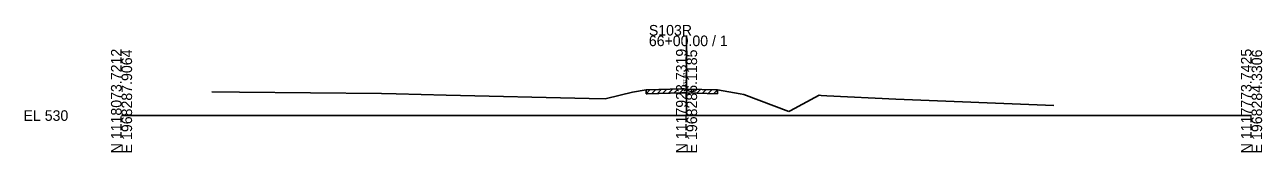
# Model space of a CAD drawing. Extents: x 974 to 1303, y 990 to 10019.
# Drawn here: x 974.3 to 1302.8, y 8490.3 to 8524 of the extents above; entities that cross this region are included whole.
import ezdxf

# ---------------------------------------------------------------- set-up
doc = ezdxf.new("R2010")
doc.units = 0
for name, color, linetype in [('Level 10', 7, 'Continuous'), ('Level 60', 7, 'Continuous'), ('Level 61', 7, 'Continuous'), ('Level 63', 7, 'Continuous')]:
    doc.layers.add(name, color=color, linetype=linetype)

msp = doc.modelspace()

# ---------------------------------------------------------------- linework, layer by layer
at = {"layer": 'Level 60'}
for p, q in [((1024, 8506.26), (1031.36, 8506.23)), ((1031.36, 8506.23), (1069.05, 8505.88)), ((1069.05, 8505.88), (1072.95, 8505.79)), ((1072.95, 8505.79), (1086.16, 8505.43)), ((1128.72, 8504.53), (1135.67, 8506.19)), ((1135.67, 8506.19), (1139.25, 8506.79)), ((1139.25, 8506.79), (1139.55, 8506.8)), ((1139.55, 8506.8), (1148.78, 8507.06)), ((1148.78, 8507.06), (1149.33, 8507.05)), ((1149.33, 8507.05), (1150, 8507.03)), ((1150, 8507.03), (1158.23, 8506.79)), ((1158.23, 8506.79), (1164.22, 8505.77)), ((1164.22, 8505.77), (1165.18, 8505.61)), ((1086.16, 8505.43), (1124.11, 8504.53)), ((1124.11, 8504.53), (1128.37, 8504.44)), ((1128.37, 8504.44), (1128.72, 8504.53)), ((1165.18, 8505.61), (1177.16, 8501.04)), ((1177.52, 8501.23), (1185.23, 8505.38)), ((1185.23, 8505.38), (1185.77, 8505.3)), ((1185.77, 8505.3), (1187.25, 8505.27)), ((1187.25, 8505.27), (1205.59, 8504.32)), ((1205.59, 8504.32), (1247.5, 8502.64)), ((1177.16, 8501.04), (1177.52, 8501.23))]:
    msp.add_line(p, q, dxfattribs=at)
at = {"layer": 'Level 61'}
for p, q in [((1139.25, 8505.79), (1140.28, 8506.82)), ((1139.25, 8505.79), (1139.25, 8506.79)), ((1139.25, 8505.79), (1139.55, 8505.8)), ((1139.55, 8505.8), (1148.78, 8506.06)), ((1140.75, 8505.83), (1141.78, 8506.86)), ((1142.25, 8505.87), (1143.28, 8506.9)), ((1143.75, 8505.92), (1144.78, 8506.95)), ((1145.25, 8505.96), (1146.28, 8506.99)), ((1146.75, 8506), (1147.78, 8507.03)), ((1148.25, 8506.05), (1149.25, 8507.05)), ((1148.78, 8506.06), (1149.33, 8506.05)), ((1149.33, 8506.05), (1150, 8506.03)), ((1149.75, 8506.03), (1150.72, 8507.01)), ((1150, 8506.03), (1158.23, 8505.79)), ((1151.25, 8505.99), (1152.22, 8506.96)), ((1152.75, 8505.95), (1153.72, 8506.92)), ((1154.25, 8505.9), (1155.22, 8506.87)), ((1155.75, 8505.86), (1156.72, 8506.83)), ((1157.25, 8505.82), (1158.22, 8506.79)), ((1158.23, 8506.79), (1158.23, 8505.79))]:
    msp.add_line(p, q, dxfattribs=at)
at = {"layer": 'Level 63'}
for p, q in [((1150, 8500), (1150, 8521.19)), ((1000, 8500), (1150, 8500)), ((1150, 8500), (1300, 8500))]:
    msp.add_line(p, q, dxfattribs=at)

# ---------------------------------------------------------------- texts
at = {"layer": 'Level 10'}
msp.add_text('537.03', height=0.9, rotation=90, dxfattribs=at).set_placement((1149.95, 8507.53))
at = {"layer": 'Level 63'}
for s, p in [('S103R', (1140, 8521.19)), ('66+00.00 / 1', (1140, 8518.39)), ('EL 530', (974, 8498.6))]:
    msp.add_text(s, height=2.8, dxfattribs=at).set_placement(p)
for s, p in [('N 1118073.7212', (1000, 8490)), ('E 1968287.9064', (1002.8, 8490)), ('N 1117923.7319', (1150, 8490)), ('E 1968286.1185', (1152.8, 8490)), ('N 1117773.7425', (1300, 8490)), ('E 1968284.3306', (1302.8, 8490))]:
    msp.add_text(s, height=2.8, rotation=90, dxfattribs=at).set_placement(p)

doc.saveas('drawing.dxf')
